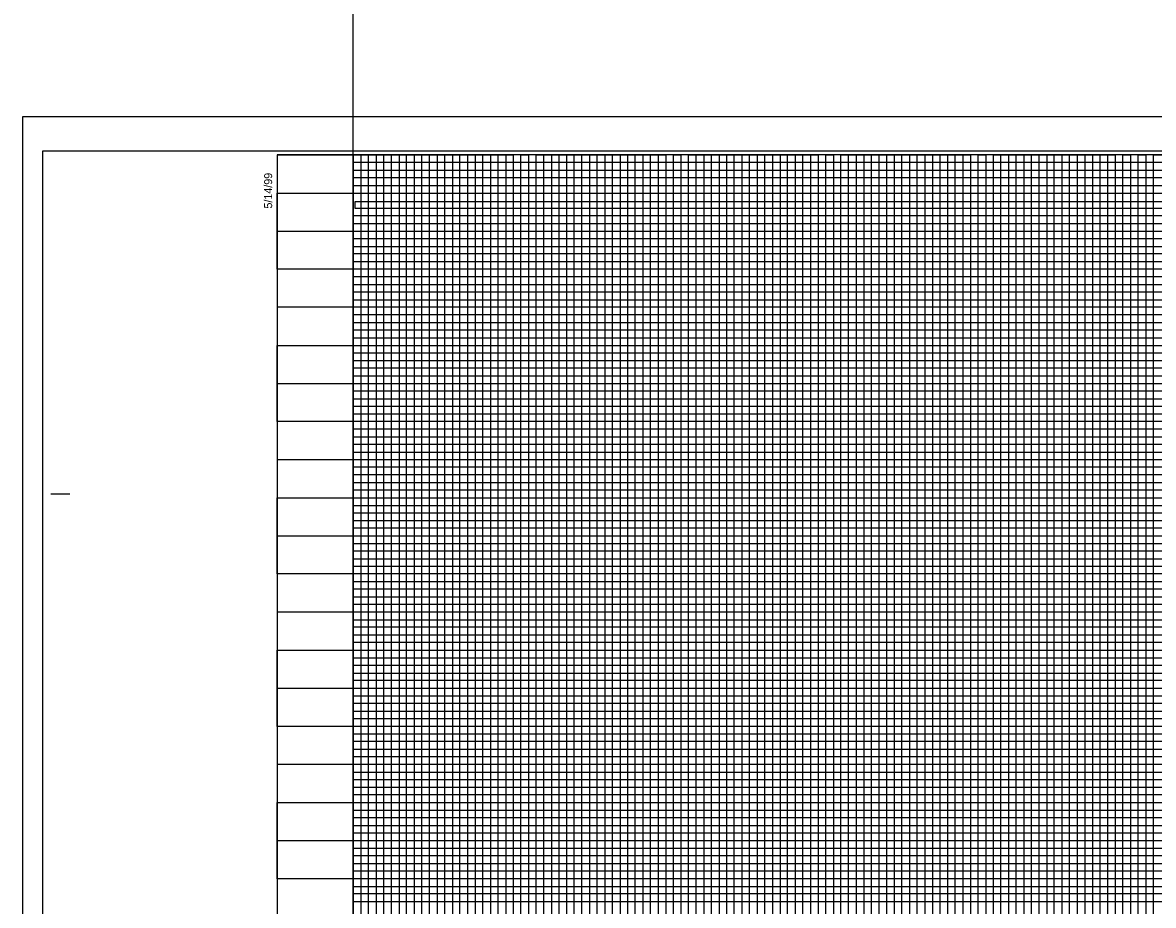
# Model space of a CAD drawing. Extents: x 2345490 to 2445302, y 465165 to 573888.
# Drawn here: x 2381550 to 2382292, y 532944 to 533523 of the extents above; entities that cross this region are included whole.
import ezdxf

# ---------------------------------------------------------------- set-up
doc = ezdxf.new("R2010")
doc.units = 0
for name, color, linetype in [('Old_Level_18', 7, 'Continuous'), ('Old_Level_41', 7, 'Continuous'), ('Old_Level_42', 7, 'Continuous'), ('Old_Level_43', 7, 'Continuous'), ('Old_Level_50', 7, 'Continuous'), ('Old_Level_51', 7, 'Continuous'), ('Old_Level_63', 7, 'Continuous')]:
    doc.layers.add(name, color=color, linetype=linetype)

msp = doc.modelspace()

# ---------------------------------------------------------------- linework, layer by layer
at = {"layer": 'Old_Level_18'}
msp.add_lwpolyline([(2383216.79875, 533436.04975), (2381716.79875, 533436.04975), (2381716.79875, 532386.04975), (2383216.79875, 532386.04975)], close=True, dxfattribs=at)
at = {"layer": 'Old_Level_41'}
msp.add_line((2381568.29875, 533213.54975), (2381580.79875, 533213.54975), dxfattribs=at)
for points in [[(2381716.79875, 533436.04975), (2381766.79875, 533436.04975), (2381766.79875, 532411.04975), (2381816.79875, 532411.04975), (2381816.79875, 533436.04975), (2381866.79875, 533436.04975), (2381866.79875, 532411.04975), (2381916.79875, 532411.04975), (2381916.79875, 533436.04975), (2381966.79875, 533436.04975), (2381966.79875, 532411.04975), (2382016.79875, 532411.04975), (2382016.79875, 533436.04975), (2382066.79875, 533436.04975), (2382066.79875, 532411.04975), (2382116.79875, 532411.04975), (2382116.79875, 533436.04975), (2382166.79875, 533436.04975), (2382166.79875, 532411.04975), (2382216.79875, 532411.04975), (2382216.79875, 533436.04975), (2382266.79875, 533436.04975), (2382266.79875, 532411.04975), (2382316.79875, 532411.04975)], [(2381791.79875, 532411.04975), (2381791.79875, 533436.04975), (2381841.79875, 533436.04975), (2381841.79875, 532411.04975), (2381891.79875, 532411.04975), (2381891.79875, 533436.04975), (2381941.79875, 533436.04975), (2381941.79875, 532411.04975), (2381991.79875, 532411.04975), (2381991.79875, 533436.04975), (2382041.79875, 533436.04975), (2382041.79875, 532411.04975), (2382091.79875, 532411.04975), (2382091.79875, 533436.04975), (2382141.79875, 533436.04975), (2382141.79875, 532411.04975), (2382191.79875, 532411.04975), (2382191.79875, 533436.04975), (2382241.79875, 533436.04975), (2382241.79875, 532411.04975), (2382291.79875, 532411.04975), (2382291.79875, 533436.04975), (2382341.79875, 533436.04975)], [(2381716.79875, 533386.04975), (2383016.74875, 533386.04975)], [(2383016.74875, 533336.04975), (2381716.79875, 533336.04975), (2381716.79875, 533285.99975), (2383216.79875, 533285.99975)], [(2383216.79875, 533261.04975), (2381716.79875, 533261.04975), (2381716.79875, 533311.04975), (2383016.74875, 533311.04975)], [(2383216.79875, 533236.04975), (2381716.79875, 533236.04975), (2381716.79875, 533186.04975), (2383216.79875, 533186.04975)], [(2383216.79875, 533161.04975), (2381716.79875, 533161.04975), (2381716.79875, 533211.04975), (2383216.79875, 533211.04975)], [(2383216.79875, 533136.04975), (2381716.79875, 533136.04975), (2381716.79875, 533086.04975), (2383216.79875, 533086.04975)], [(2383216.79875, 533036.04975), (2381716.79875, 533036.04975), (2381716.79875, 532986.04975), (2383216.79875, 532986.04975)]]:
    msp.add_lwpolyline(points, dxfattribs=at)
at = {"layer": 'Old_Level_42'}
for points in [[(2383016.74875, 533361.04975), (2381716.89875, 533361.04975), (2381716.89875, 533410.99975), (2383016.74875, 533410.99975)], [(2383216.79875, 533061.04975), (2381716.79875, 533061.04975), (2381716.79875, 533111.04975), (2383216.79875, 533111.04975)], [(2383216.79875, 532961.04975), (2381716.79875, 532961.04975), (2381716.79875, 533011.04975), (2383216.79875, 533011.04975)]]:
    msp.add_lwpolyline(points, dxfattribs=at)
at = {"layer": 'Old_Level_43'}
for p, q in [((2383166.79875, 533256.04975), (2381766.79875, 533256.04975)), ((2381766.79875, 533256.04975), (2381766.79875, 533251.04975)), ((2381766.79875, 533251.04975), (2383166.79875, 533251.04975)), ((2383166.79875, 533231.04975), (2381766.79875, 533231.04975))]:
    msp.add_line(p, q, dxfattribs=at)
for points in [[(2381771.79875, 533436.04975), (2381776.79875, 533436.04975), (2381781.79875, 533436.04975), (2381786.79875, 533436.04975), (2381796.79875, 533436.04975), (2381763.74875, 533436.04975), (2381768.74875, 533436.04975), (2381726.79875, 533436.04975), (2381731.79875, 533436.04975), (2381736.79875, 533436.04975), (2381746.79875, 533436.04975), (2381751.79875, 533436.04975), (2381756.79875, 533436.04975), (2381761.79875, 533436.04975), (2381771.79875, 533436.04975), (2381771.79875, 532411.04975)], [(2381776.79875, 532411.04975), (2381776.79875, 533436.04975), (2381781.79875, 533436.04975), (2381781.79875, 532411.04975)], [(2381786.79875, 532411.04975), (2381786.79875, 533436.04975), (2381796.79875, 533436.04975), (2381796.79875, 532411.04975)], [(2381801.79875, 532411.04975), (2381801.79875, 533436.04975), (2381806.79875, 533436.04975), (2381806.79875, 532411.04975)], [(2381811.79875, 532411.04975), (2381811.79875, 533436.04975), (2381821.79875, 533436.04975), (2381821.79875, 532411.04975)], [(2381826.79875, 532411.04975), (2381826.79875, 533436.04975), (2381831.79875, 533436.04975), (2381831.79875, 532411.04975)], [(2381836.79875, 532411.04975), (2381836.79875, 533436.04975), (2381846.79875, 533436.04975), (2381846.79875, 532411.04975)], [(2381851.79875, 532411.04975), (2381851.79875, 533436.04975), (2381856.79875, 533436.04975), (2381856.79875, 532411.04975)], [(2381861.79875, 532411.04975), (2381861.79875, 533436.04975), (2381871.79875, 533436.04975), (2381871.79875, 532411.04975)], [(2381876.79875, 532411.04975), (2381876.79875, 533436.04975), (2381881.79875, 533436.04975), (2381881.79875, 532411.04975)], [(2381886.79875, 532411.04975), (2381886.79875, 533436.04975), (2381896.79875, 533436.04975), (2381896.79875, 532411.04975)], [(2381901.79875, 532411.04975), (2381901.79875, 533436.04975), (2381906.79875, 533436.04975), (2381906.79875, 532411.04975)], [(2381911.79875, 532411.04975), (2381911.79875, 533436.04975), (2381921.79875, 533436.04975), (2381921.79875, 532411.04975)], [(2381926.79875, 532411.04975), (2381926.79875, 533436.04975), (2381931.79875, 533436.04975), (2381931.79875, 532411.04975)], [(2381936.79875, 532411.04975), (2381936.79875, 533436.04975), (2381946.79875, 533436.04975), (2381946.79875, 532411.04975)], [(2381951.79875, 532411.04975), (2381951.79875, 533436.04975), (2381956.79875, 533436.04975), (2381956.79875, 532411.04975)], [(2381961.79875, 532411.04975), (2381961.79875, 533436.04975), (2381971.79875, 533436.04975), (2381971.79875, 532411.04975)], [(2381976.79875, 532411.04975), (2381976.79875, 533436.04975), (2381976.79875, 533436.04975), (2381981.79875, 533436.04975), (2381981.79875, 532411.04975)], [(2381986.79875, 532411.04975), (2381986.79875, 533436.04975), (2381996.79875, 533436.04975), (2381996.79875, 532411.04975)], [(2382001.79875, 532411.04975), (2382001.79875, 533436.04975), (2382006.79875, 533436.04975), (2382006.79875, 532411.04975)], [(2382011.79875, 532411.04975), (2382011.79875, 533436.04975), (2382021.79875, 533436.04975), (2382021.79875, 532411.04975)], [(2382026.79875, 532411.04975), (2382026.79875, 533436.04975), (2382031.79875, 533436.04975), (2382031.79875, 532411.04975)], [(2382036.79875, 532411.04975), (2382036.79875, 533436.04975), (2382046.79875, 533436.04975), (2382046.79875, 532411.04975)], [(2382051.79875, 532411.04975), (2382051.79875, 533436.04975), (2382056.79875, 533436.04975), (2382056.79875, 532411.04975)], [(2382061.79875, 532411.04975), (2382061.79875, 533436.04975), (2382071.79875, 533436.04975), (2382071.79875, 532411.04975)], [(2382076.79875, 532411.04975), (2382076.79875, 533436.04975), (2382081.79875, 533436.04975), (2382081.79875, 532411.04975)], [(2382086.79875, 532411.04975), (2382086.79875, 533436.04975), (2382096.79875, 533436.04975), (2382096.79875, 532411.04975)], [(2382101.79875, 533436.04975), (2382101.79875, 532411.04975), (2382106.79875, 532411.04975), (2382106.79875, 533436.04975)], [(2382101.79875, 533435.44975), (2382101.79875, 532411.04975), (2382106.79875, 532411.04975), (2382106.79875, 533435.44975)], [(2382111.79875, 532411.04975), (2382111.79875, 533436.04975), (2382121.79875, 533436.04975), (2382121.79875, 532411.04975)], [(2382126.79875, 532411.04975), (2382126.79875, 533436.04975), (2382131.79875, 533436.04975), (2382131.79875, 532411.04975)], [(2382136.79875, 532411.04975), (2382136.79875, 533436.04975), (2382146.79875, 533436.04975), (2382146.79875, 532411.04975)], [(2382151.79875, 532411.04975), (2382151.79875, 533436.04975), (2382156.79875, 533436.04975), (2382156.79875, 532411.04975)], [(2382161.79875, 532411.04975), (2382161.79875, 533436.04975), (2382171.79875, 533436.04975), (2382171.79875, 532411.04975)], [(2382176.79875, 532411.04975), (2382176.79875, 533436.04975), (2382181.79875, 533436.04975), (2382181.79875, 532411.04975)], [(2382186.79875, 532411.04975), (2382186.79875, 533436.04975), (2382196.79875, 533436.04975), (2382196.79875, 532411.04975)], [(2382201.79875, 532411.04975), (2382201.79875, 533436.04975), (2382206.79875, 533436.04975), (2382206.79875, 532411.04975)], [(2382211.79875, 532411.04975), (2382211.79875, 533436.04975), (2382221.79875, 533436.04975), (2382221.79875, 532411.04975)], [(2382226.79875, 532411.04975), (2382226.79875, 533436.04975), (2382231.79875, 533436.04975), (2382231.79875, 532411.04975)], [(2382236.79875, 532411.04975), (2382236.79875, 533436.04975), (2382246.79875, 533436.04975), (2382246.79875, 532411.04975)], [(2382251.79875, 533436.04975), (2382251.79875, 532411.04975), (2382256.79875, 532411.04975), (2382256.79875, 533436.04975), (2382261.79875, 533436.04975), (2382261.79875, 532411.04975), (2382271.79875, 532411.04975), (2382271.79875, 533436.04975), (2382276.79875, 533436.04975), (2382276.79875, 532411.04975), (2382281.79875, 532411.04975), (2382281.79875, 533436.04975), (2382286.79875, 533436.04975), (2382286.79875, 532411.04975)], [(2383016.74875, 533431.04975), (2381766.79875, 533431.04975), (2381766.79875, 533426.04975), (2383016.74875, 533426.04975)], [(2383016.74875, 533421.04975), (2381766.79875, 533421.04975), (2381766.79875, 533416.04975), (2383016.74875, 533416.04975)], [(2383016.74875, 533405.29975), (2381767.79875, 533405.29975), (2381767.79875, 533401.04975), (2383016.74875, 533401.04975)], [(2383016.74875, 533396.04975), (2381766.79875, 533396.04975), (2381766.79875, 533391.04975), (2383016.74875, 533391.04975)], [(2383016.74875, 533381.04975), (2381766.79875, 533381.04975), (2381766.79875, 533376.04975), (2383016.74875, 533376.04975)], [(2383016.74875, 533371.04975), (2381766.79875, 533371.04975), (2381766.79875, 533366.04975), (2383016.74875, 533366.04975)], [(2383016.74875, 533356.04975), (2381766.79875, 533356.04975), (2381766.79875, 533351.04975), (2383016.74875, 533351.04975)], [(2383016.74875, 533346.04975), (2381766.79875, 533346.04975), (2381766.79875, 533341.04975), (2383016.74875, 533341.04975)], [(2383016.74875, 533331.04975), (2381766.79875, 533331.04975), (2381766.79875, 533326.04975), (2383016.74875, 533326.04975)], [(2383016.74875, 533321.04975), (2381766.79875, 533321.04975), (2381766.79875, 533316.04975), (2383016.74875, 533316.04975)], [(2383016.74875, 533306.04975), (2381766.79875, 533306.04975), (2381766.79875, 533301.04975), (2383016.74875, 533301.04975)], [(2383166.79875, 533296.04975), (2381766.79875, 533296.04975), (2381766.79875, 533296.04975), (2381766.79875, 533276.04975), (2383166.79875, 533276.04975)], [(2381766.79875, 533291.04975), (2383166.79875, 533291.04975)], [(2383166.79875, 533281.04975), (2381766.79875, 533281.04975)], [(2383166.79875, 533271.04975), (2381766.79875, 533271.04975), (2381766.79875, 533266.04975), (2383166.79875, 533266.04975)], [(2383166.79875, 533246.04975), (2381766.79875, 533246.04975), (2381766.79875, 533241.04975), (2383166.79875, 533241.04975)], [(2383166.79875, 533226.04975), (2381766.79875, 533226.04975), (2381766.79875, 533221.04975), (2383166.79875, 533221.04975)], [(2383166.79875, 533216.04975), (2381766.79875, 533216.04975)], [(2381766.79875, 533206.04975), (2383166.79875, 533206.04975)], [(2383166.79875, 533201.04975), (2381766.79875, 533201.04975), (2381766.79875, 533196.04975), (2383166.79875, 533196.04975)], [(2383166.79875, 533191.04975), (2381766.79875, 533191.04975), (2381766.79875, 533181.04975), (2383166.79875, 533181.04975)], [(2383166.79875, 533176.04975), (2381766.79875, 533176.04975), (2381766.79875, 533171.04975), (2383166.79875, 533171.04975)], [(2383166.79875, 533166.04975), (2381766.79875, 533166.04975), (2381766.79875, 533156.04975), (2383166.79875, 533156.04975)], [(2383166.79875, 533151.04975), (2381766.79875, 533151.04975), (2381766.79875, 533146.04975), (2383166.79875, 533146.04975)], [(2383166.79875, 533141.04975), (2381766.79875, 533141.04975), (2381766.79875, 533131.04975), (2383166.79875, 533131.04975)], [(2383166.79875, 533126.04975), (2381766.79875, 533126.04975), (2381766.79875, 533121.04975), (2383166.79875, 533121.04975)], [(2383166.79875, 533116.04975), (2381766.79875, 533116.04975), (2381766.79875, 533106.04975), (2383166.79875, 533106.04975)], [(2383166.79875, 533101.04975), (2381766.79875, 533101.04975), (2381766.79875, 533096.04975), (2383166.79875, 533096.04975)], [(2383166.79875, 533091.04975), (2381766.79875, 533091.04975), (2381766.79875, 533081.04975), (2383166.79875, 533081.04975)], [(2383166.79875, 533076.04975), (2381766.79875, 533076.04975), (2381766.79875, 533071.04975), (2383166.79875, 533071.04975)], [(2383166.79875, 533066.04975), (2381766.79875, 533066.04975), (2381766.79875, 533056.04975), (2383166.79875, 533056.04975)], [(2383166.79875, 533051.04975), (2381766.79875, 533051.04975), (2381766.79875, 533046.04975), (2383166.79875, 533046.04975)], [(2383166.79875, 533041.04975), (2381766.79875, 533041.04975), (2381766.79875, 533031.04975), (2383166.79875, 533031.04975)], [(2383166.79875, 533026.04975), (2381766.79875, 533026.04975), (2381766.79875, 533021.04975), (2383166.79875, 533021.04975)], [(2383166.79875, 533016.04975), (2381766.79875, 533016.04975), (2381766.79875, 533006.04975), (2383166.79875, 533006.04975)], [(2383166.79875, 533001.04975), (2381766.79875, 533001.04975), (2381766.79875, 532996.04975), (2383166.79875, 532996.04975)], [(2383166.79875, 532991.04975), (2381766.79875, 532991.04975), (2381766.79875, 532981.04975), (2383166.79875, 532981.04975)], [(2383166.79875, 532976.04975), (2381766.79875, 532976.04975), (2381766.79875, 532971.04975), (2383166.79875, 532971.04975)], [(2383166.79875, 532966.04975), (2381766.79875, 532966.04975), (2381766.79875, 532956.04975), (2383166.79875, 532956.04975)], [(2383166.79875, 532951.04975), (2381766.79875, 532951.04975), (2381766.79875, 532946.04975), (2383166.79875, 532946.04975)]]:
    msp.add_lwpolyline(points, dxfattribs=at)
at = {"layer": 'Old_Level_50'}
msp.add_lwpolyline([(2383229.29875, 533438.59975), (2381562.79875, 533438.59975), (2381562.79875, 532383.49975), (2383229.29875, 532383.49975)], close=True, dxfattribs=at)
at = {"layer": 'Old_Level_51'}
msp.add_lwpolyline([(2383233.79875, 533461.04975), (2381549.79875, 533461.04975), (2381549.79875, 532361.04975), (2383233.79875, 532361.04975)], close=True, dxfattribs=at)
at = {"layer": 'Old_Level_63'}
msp.add_line((2381766.79875, 532411.04975), (2381766.79875, 534911.04975), dxfattribs=at)

# ---------------------------------------------------------------- texts
at = {"layer": 'Old_Level_41'}
msp.add_text('5/14/99', height=5.25, rotation=90, dxfattribs=at).set_placement((2381713.54875, 533400.84975))

doc.saveas('drawing.dxf')
